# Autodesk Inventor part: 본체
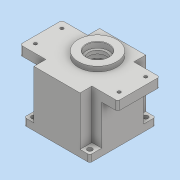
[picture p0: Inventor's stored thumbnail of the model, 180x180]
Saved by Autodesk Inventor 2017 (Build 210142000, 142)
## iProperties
Part Number: 본체
Material: 일반
Document SubType Name: Modeling
Designer: user
Density: 1 g/cm^3
Appearance: 기본값
Author: user
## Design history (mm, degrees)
sketch "스케치1"
  geometry: L1 (37, 47)-(103, 47); L2 (103, 47)-(103, 30); L3 (103, 30)-(140, 30); L4 (140, 30)-(140, -30); L5 (140, -30)-(103, -30); L6 (103, -30)-(103, -47); L7 (103, -47)-(37, -47); L8 (37, -47)-(37, -30); L9 (37, -30)-(0, -30); L10 (0, -30)-(0, 30); L11 (0, 30)-(37, 30); L12 (37, 30)-(37, 47); 1 further point
  constraints: 24 end point, 4 parallel, 3 horizontal, 3 vertical, 2 collinear, 2 midpoint, 2 perpendicular, 1 point on line
  dimensions: "d0" = 66 distance of L1.start L1.end; "d1" = 140 distance between parallel lines of L10 L4; "d2" = 66 distance of L6.end L7.end; "d3" = 37 distance between parallel lines of L10 L12; "d4" = 94 distance between parallel lines of L7 L1; "d5" = 60 distance between parallel lines of L5 L3; "d6" = 17 distance of L1.end L2.end
extrude "돌출1" new body sketch "스케치1" distance "d7" = 13; taper "d8" = 0 deg
sketch "스케치2"
  geometry: L1 (-103, -47)-(-103, -30); L2 (-103, -30)-(-117, -30); L3 (-117, -30)-(-117, 30); L4 (-117, 30)-(-103, 30); L5 (-103, 30)-(-103, 47); L6 (-103, 47)-(-37, 47); L7 (-37, 47)-(-37, 30); L8 (-37, 30)-(-23, 30); L9 (-23, 30)-(-23, -30); L10 (-23, -30)-(-37, -30); L11 (-37, -30)-(-37, -47); L12 (-37, -47)-(-103, -47); 9 further points
  constraints: 25 end point, 8 coincident, 4 perpendicular, 3 point on line, 2 parallel, 1 horizontal
  dimensions: "d9" = 94 distance between parallel lines of L9 L3; "d10" = 14 distance of L1.end L2.end
extrude "돌출2" join sketch "스케치2" distance "d11" = 57; taper "d12" = 0 deg
sketch "스케치3"
  geometry: L1 (-117, 47)-(-23, 47); L2 (-23, 47)-(-23, -47); L3 (-23, -47)-(-117, -47); L4 (-117, -47)-(-117, 47); L5 (-117, 47)-(-23, -47); L6 (-23, 47)-(-117, -47); L7 (-103, -47)-(-37, -47) reference; L8 (-23, -30)-(-23, 30) reference; 2 further points
  constraints: 12 end point, 2 collinear, 2 midpoint, 2 parallel, 1 horizontal, 1 perpendicular
  dimensions: "d13" = 94 distance of L2.end L3.end; "d14" = 94 distance of L3.end L1.start
extrude "돌출3" join sketch "스케치3" distance "d15" = 10; taper "d16" = 0 deg
sketch "스케치4"
  geometry: L1 (0, -30)-(0, 30) reference; L2 (-23, -47)-(-23, 47) reference; C1 r 43 at (-70, 0); 2 further points
  constraints: 1 centre point, 1 coincident, 1 horizontal alignment, 1 midpoint
  dimensions: "d17" = 86 diameter of C1; "d18" = 47 distance from line of C1.centre L2
extrude "돌출4" cut sketch "스케치4" distance "d19" = 9; taper "d20" = 0 deg
sketch "스케치5"
  geometry: C1 r 40 at (0, 0); C2 r 43 at (0, 0) reference; 1 further point
  constraints: 1 centre point, 1 concentric
  dimensions: "d21" = 80 diameter of C1
extrude "돌출5" cut sketch "스케치5" distance "d22" = 62; taper "d23" = 0 deg
sketch "스케치6"
  geometry: L1 (37, -47)-(103, -47) reference; C1 r 40 at (70, 0) reference; C2 r 43 at (70, 0) reference; C3 r 27.5 at (70, 11); 1 further point
  constraints: 1 centre point, 1 vertical alignment
  dimensions: "d24" = 55 diameter of C3; "d25" = 58 distance from line of L1 C3.centre
extrude "돌출6" join sketch "스케치6" distance "d26" = 7; taper "d27" = 0 deg
sketch "스케치7"
  geometry: C1 r 16 at (0, 0); C2 r 27.5 at (0, 0) reference; 1 further point
  constraints: 1 centre point, 1 concentric
  dimensions: "d28" = 32 diameter of C1
extrude "돌출7" cut sketch "스케치7" distance "d29" = 8.3; taper "d30" = 0 deg
sketch "스케치8"
  geometry: C1 r 12.5 at (0, 0); C2 r 16 at (0, 0) reference; 1 further point
  constraints: 1 centre point, 1 concentric
  dimensions: "d31" = 25 diameter of C1
extrude "돌출8" cut sketch "스케치8" distance "d32" = 4.7; taper "d33" = 0 deg
sketch "스케치10" dims "d17" = 86
  geometry: C1 r 17.5 at (0, 0); C2 r 16 at (0, 0) reference; C3 r 27.5 at (0, 0) reference; 1 further point
  constraints: 1 centre point, 1 coincident
  dimensions: "d34" = 35 diameter of C1
extrude "돌출9" cut sketch "스케치10" distance "d35" = 10; taper "d36" = 0 deg
node "작업 평면2"
sketch "스케치14"
  geometry: C1 r 21 at (0, 11); C2 r 15 at (0, -20); C3 r 40 at (0, 0) reference; 1 further point
  constraints: 2 centre point, 2 vertical alignment
  dimensions: "d42" = 42 diameter of C1; "d43" = 30 diameter of C2; "d44" = 11 distance of C3.centre C1.centre; "d45" = 20 distance of C2.centre C3.centre
extrude "돌출11" join sketch "스케치14" distance "d46" = 7; taper "d47" = 0 deg
sketch "스케치15"
  geometry: L1 (33, 36)-(33, 19) reference; L2 (33, 19)-(70, 19) reference; L3 (70, 19)-(70, -41) reference; L4 (70, -41)-(33, -41) reference; L5 (33, -41)-(33, -58) reference; L6 (33, -58)-(-33, -58) reference; L7 (-33, -58)-(-33, -41) reference; L8 (-33, -41)-(-70, -41) reference; L9 (-70, -41)-(-70, 19) reference; L10 (-70, 19)-(-33, 19) reference; L11 (-33, 19)-(-33, 36) reference; L12 (-33, 36)-(33, 36) reference; C1 r 16 at (0, 0) reference; C2 r 40 at (0, -11) reference; A1 r 21 centre (0, 0) between (8.978, -18.984) and (-8.978, -18.984) reference; A2 r 15 centre (0, -31) between (-8.978, -18.984) and (8.978, -18.984) reference; 1 further point
extrude "돌출12" cut sketch "스케치15" distance "d48" = 33.75; taper "d49" = 0 deg
sketch "스케치16"
  geometry: C1 r 11 at (0, -20); A1 r 15 centre (0, -20) between (-8.978, -7.984) and (8.978, -7.984) reference; 1 further point
  constraints: 1 centre point, 1 coincident, 1 concentric
  dimensions: "d50" = 22 diameter of C1
extrude "돌출13" cut sketch "스케치16" distance "d51" = 7; taper "d52" = 0 deg
sketch "스케치17"
  geometry: C1 r 11 at (0, 0) reference; C2 r 9.5 at (0, 0); 1 further point
  constraints: 1 centre point, 1 concentric
  dimensions: "d53" = 19 diameter of C2
extrude "돌출14" cut sketch "스케치17" distance "d54" = 3; taper "d55" = 0 deg
sketch "스케치19"
  geometry: L1 (140, 30)-(140, -30) reference; L2 (117, 30)-(140, 30) reference; C1 r 2.25 at (130, -18); C2 r 2.25 at (130, 20); C3 r 16 at (70, 11) reference; 1 further point
  constraints: 2 centre point, 1 vertical alignment
  dimensions: "d58" = 4.5 diameter of C1; "d59" = 4.5 diameter of C2; "d61" = 38 distance of C1.centre C2.centre; "d64" = 10 distance from line of L1 C2.centre; "d65" = 10 distance from line of L2 C2.centre
extrude "돌출15" cut sketch "스케치19" distance "d66" = 8; taper "d67" = 0 deg
sketch "스케치20"
  geometry: C1 r 2.25 at (-130, 20) reference; C2 r 2.25 at (-130, -18) reference; C3 r 5 at (-130, -18); C4 r 5 at (-130, 20); 1 further point
  constraints: 2 centre point, 2 concentric
  dimensions: "d68" = 10 diameter of C3; "d69" = 10 diameter of C4
extrude "돌출16" cut sketch "스케치20" distance "d70" = 5; taper "d71" = 0 deg
node "작업 평면3"
sketch "스케치23"
  geometry: L1 (117, -47)-(23, -47) reference; L2 (117, 47)-(117, -47) reference; C1 r 3.5 at (110, 40); C2 r 3.5 at (110, -40); C3 r 16 at (70, 11) reference; C4 r 27.5 at (70, 11) reference; 1 further point
  constraints: 2 centre point, 1 vertical alignment
  dimensions: "d77" = 7 diameter of C1; "d78" = 7 diameter of C2; "d79" = 80 distance of C2.centre C1.centre; "d80" = 7 distance from line of L1 C2.centre; "d81" = 7 distance from line of L2 C2.centre
extrude "돌출17" cut sketch "스케치23" distance "d82" = 10; taper "d83" = 0 deg
node "작업 평면4"
sketch "스케치24"
  geometry: A1 r 40 centre (0, 0) between (39.279, 7.559) and (39.279, -7.559) reference; A2 r 4 centre (36, 0) between (36.19, 3.995) and (36.19, -3.995); A3 r 3 centre (36.333, 6.992) between (36.19, 3.995) and (39.279, 7.559); A4 r 3 centre (36.333, -6.992) between (39.279, -7.559) and (36.19, -3.995); 1 further point
  constraints: 8 point on circle, 4 tangent, 3 centre point, 1 horizontal alignment
  dimensions: "d85" = 8 diameter of A2; "d86" = 36 distance of A1.centre A2.centre; "d87" = 3 radius of A3; "d88" = 3 radius of A4
extrude "돌출18" join sketch "스케치24" stored distance "d89" = 0; taper "d90" = 0 deg
chamfer "모따기1" distance "d91" = 0.8; stored, may be unused: second distance "d92" = 2, angle "d93" = 30 deg
sketch "스케치26"
  geometry: L1 (-14, 80)-(80, 80) reference; L2 (5.5, -7)-(60.5, -7) reference; L3 (60.5, 0)-(5.5, 0) reference; L4 (0, 70)-(0, 0) reference; 2 further points
  constraints: 1 other
  dimensions: "d97" = 40 distance from line of L1 point (33, 40); "d98" = 33 distance from line of L4 point (33, 40)
feature "엠보싱1" sketch "스케치26" dims "d0" = 66, "d1" = 140, "d2" = 66, "d3" = 37, "d4" = 94, "d5" = 60, "d6" = 17, "d9" = 94, "d10" = 14, "d99" = 0.5, "d100" = 0
hole "구멍1" diameter "d103" = 3.242; stored, may be unused: countersink angle "d107" = 90 deg, drill point angle "d109" = 118 deg; dims "d101" = 10, "d102" = 10, "d104" = 7, "d105" = 4, "d106" = 2, "d108" = 9
fillet "모깎기1" dims "d110" = 3
chamfer "모따기2" distance "d111" = 1; stored, may be unused: second distance "d112" = 2, angle "d113" = 30 deg
chamfer "모따기3" distance "d114" = 1; stored, may be unused: second distance "d115" = 2, angle "d116" = 30 deg
fillet "모깎기2" dims "d117" = 3
sketch "스케치27"
  geometry: C1 r 17.5 at (0, 11); C2 r 16 at (0, 11) reference; 1 further point
  constraints: 1 centre point, 1 concentric
  dimensions: "d118" = 35 diameter of C1
extrude "돌출20" cut sketch "스케치27" distance "d119" = 10; taper "d120" = 0 deg
chamfer "모따기4" distance "d121" = 1; stored, may be unused: second distance "d122" = 2, angle "d123" = 30 deg
node "솔리드1"
mirror "미러1"
mirror "미러2"
mirror "미러3"
mirror "미러5"
node "투영된 루프1"
node "투영된 루프2"
node "투영된 루프3"
node "절단 모서리 투영1"
other parameters: "d37" = 0
